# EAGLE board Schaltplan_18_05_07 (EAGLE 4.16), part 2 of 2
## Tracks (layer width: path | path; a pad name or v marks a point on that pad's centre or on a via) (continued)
N$105  (via drill 0.5) (continued)
  Top 0.305: R39.2 232.41,43.18 233.07,42.52 S3.P$1 233.04,35.56 235.59,33.02 235.59,9.53 233.68,7.62 224.79,7.62 222.57,5.4 186.06,5.4 182.88,8.57 182.88,35.56 177.8,40.64 177.8,53.98 184.78,60.96 184.78,67.94 189.87,73.03 193.68,73.03 194.31,72.39 v194.31,71.12 | IC15.3 v194.31,68.58
  Bottom 0.305: v194.31,68.58 v194.31,71.12
N$106  (via drill 0.5)
  Top 0.305: v229.87,31.11 S3.P$2 | v161.93,53.98 146.69,69.22 IC13.2
  Bottom 0.305: v229.87,31.11 223.52,24.77 191.13,24.77 v161.93,53.98
N$107
  Top 0.305: IC15.2 195.58,64.77 196.22,64.14 201.29,64.14 C26.2
N$108  (via drill 0.5)
  Top 0.305: 228.6,14.61 T3.1 | 228.6,43.81 R41.2 228.6,14.61 | C26.1 201.29,71.12 198.12,74.3 188.59,74.3 182.88,68.58 182.88,60.96 176.53,54.61 176.53,40.01 181.61,34.92 181.61,8.26 185.42,4.45 224.16,4.45 226.06,6.35 v228.6,6.35 | v228.6,11.43 228.6,14.61
  Bottom 0.305: v228.6,6.35 v228.6,11.43
N$109  (via drill 0.5)
  Top 0.305: 215.26,50.8 217.17,52.7 223.44,52.7 D13.A 225.43,50.8 v222.88,50.8 | D12.C 215.26,50.8 | 215.26,50.8 v212.09,50.8 | 248.92,53.34 R42.2 v246.38,53.34 | v149.86,71.75 IC13.4
  Bottom 0.305: v222.88,50.8 243.84,50.8 v246.38,53.34 | v212.09,50.8 170.81,50.8 v149.86,71.75
N$110  (via drill 0.5)
  Top 0.305: D15.C 240.66,50.8 238.76,52.7 228.6,52.7 227.97,52.07 227.97,48.26 | 220.34,48.26 227.97,48.26 | 220.34,50.8 D14.A 220.34,48.26 | R43.2 236.22,46.35 234.31,48.26 227.97,48.26 | v217.81,48.26 220.34,48.26 | v149.86,73.03 IC13.5
  Bottom 0.305: v217.81,48.26 217.81,50.8 214.63,53.98 200.03,53.98 198.12,55.88 167,55.88 v149.86,73.03
N$111  (via drill 0.5 pad 0.3)
  Top 0.305: 236.22,43.81 R43.1 v236.22,41.91
  Bottom 0.305: B_P7.7.1 252.73,30.48 246.38,30.48 236.22,40.64 v236.22,41.91
N$112
  Top 0.305: T3.3 233.68,13.34 229.24,8.89 224.79,8.89 223.52,10.16 223.52,34.29 224.79,35.56 S3.P$3 | S3.P$3 226.69,35.56 | R40.1 224.79,43.81 226.67,41.94 S3.P$3
N$113
  Top 0.305: R45.1 59.05,104.78 R44.E
N$114
  Top 0.305: SPEAKER.- 42.86,121.92 43.81,122.87 60.33,122.87 61.28,121.92 61.28,104.78 R45.2
N$115
  Top 0.305: 189.87,52.07 IC14.8 189.87,50.16 | 189.87,50.16 204.44,35.59 | 204.44,35.59 204.47,35.56 | 189.87,50.16 185.42,50.16 184.78,50.8 IC14.12 184.78,52.07 | S2.P$3 208.28,35.56 208.28,35.59 204.44,35.59
N$116
  Top 0.305: IC14.10 187.32,52.07 187.22,51.97 IC14.11
N$117
  Top 0.305: T2.3 213.68,14.61 212.72,15.56 212.72,29.84 | R47.1 209.55,43.81 214.66,38.71 S2.P$1 214.63,35.56 214.63,30.48 214,29.84 212.72,29.84 | IC14.13 183.51,50.16 184.15,49.53 189.23,49.53 208.91,29.84 212.72,29.84
N$118  (via drill 0.5)
  Top 0.305: S1.P$1 196.22,35.56 | S1.P$1 198.12,35.56 199.39,34.29 199.39,15.88 198.12,14.61 T1.3 196.85,9.53 198.12,8.26 216.85,8.26 218.44,9.84 218.44,38.52 R36.1 | S1.P$1 196.24,38.71 v193.68,41.27 | v189.23,41.27 188.59,41.27 187.32,42.55 IC14.5
  Bottom 0.305: v193.68,41.27 v189.23,41.27
N$119  (via drill 0.5, 0.5 pad 0.3)
  Top 0.305: R59.2 170.81,69.85 169.54,71.12 v168.28,71.12 | v163.19,71.12 JP7.2 155.57,68.58 v152.4,65.41 | IC13.19 120.65,69.22 121.28,68.58 v121.28,65.09 | IC13.1 129.54,67.94 v129.54,65.09
  Bottom 0.305: v163.19,71.12 v168.28,71.12 | v121.28,65.09 v129.54,65.09 152.08,65.09 v152.4,65.41
N$120  (via drill 0.5)
  Top 0.305: T2.1 203.2,14.61 201.93,15.88 v201.93,31.75 | v201.93,40.32 201.93,43.81 | IC14.9 188.59,53.34 189.23,53.98 195.58,53.98 196.85,52.7 196.85,45.09 198.12,43.81 201.93,43.81 | 201.93,43.81 R46.1
  Bottom 0.305: v201.93,31.75 v201.93,40.32
N$121
  Top 0.305: B_P7.6.1 252.73,53.34 R42.1 250.19,53.34
N$122
  Top 0.305: R48.1 254,5.71 B_P3.3.1
N$123  (via drill 0.5)
  Top 0.305: IC17.1 43.18,67.94 C34.+ C33.+ 43.19,74.29 42.55,74.93 38.73,74.93 38.1,75.56 38.1,76.83 37.47,77.47 v31.75,77.47 31.75,74.3 C32.1 | JP9.1 10.79,64.14 13.97,67.31 20.95,67.31 v24.13,70.48
  Bottom 0.305: v24.13,70.48 30.8,70.48 31.75,71.44 v31.75,77.47
N$125
  Top 0.305: 33.02,98.42 R49.2 OK1.3
N$126  (via drill 0.5)
  Top 0.305: OK1.6 24.13,98.42 25.4,97.16 31.11,97.16 v32.38,95.89 32.38,93.34 R50.2 | IC16.1 43.81,99.06 43.18,98.42 38.73,98.42 38.1,97.79 v38.1,95.89
  Bottom 0.305: v32.38,95.89 v38.1,95.89
N$127
  Top 0.305: OK2.3 17.78,81.92 16.51,83.19 16.51,98.42 17.78,99.69 22.23,99.69 26.67,104.14 R51.1
N$128
  Top 0.305: R51.2 39.37,104.14 40.01,103.5 IC16.4 40.01,100.97
N$129
  Top 0.305: L10.1 40.01,85.09 38.73,86.36 36.2,86.36 34.92,87.63 34.92,98.42 R49.1
N$130
  Top 0.305: L11.1 39.96,78.15 39.01,78.15 35.24,81.92 32.7,81.92 R52.1 32.7,82.23 32.38,81.92 OK2.6
N$131  (via drill 0.5)
  Top 0.305: v38.1,93.34 40.64,93.34 41.27,93.98 IC16.6 | CAN.2 15.04,87.2 v15.24,87
  Bottom 0.305: v38.1,93.34 38.1,90.81 36.83,89.53 17.78,89.53 v15.24,87
N$132
  Top 0.305: 6.99,71.75 6.99,95.89 8.08,96.98 11.25,96.98 11.43,97.16 CAN.G1 | 6.99,71.75 11.43,71.75 CAN.G2 | 6.99,71.75 6.99,69.22 2.54,64.77 2.54,60.96 3.81,59.69 12.06,59.69 13.34,60.96 13.34,64.14 15.24,66.04 20.32,66.04 22.23,64.14 22.23,62.23 23.81,60.64 30.16,60.64 31.75,62.23 31.75,62.87 C37.1
N$133  (via drill 0.5)
  Top 0.305: CAN.7 13.87,85.83 v13.97,85.72 | 42.55,95.89 IC16.7 v42.55,93.34
  Bottom 0.305: v13.97,85.72 34.92,85.72 v42.55,93.34
N$134
  Top 0.305: S4.16 140.34,26.04 141.29,26.99 | R53.1 144.15,31.11 144.15,29.84 141.29,26.99 | 141.29,26.99 140.97,27.3 IC18.2
N$135
  Top 0.305: R54.1 144.78,34.92 145.41,34.29 145.41,29.21 142.88,26.67 S4.15 142.88,22.23 142.24,21.59 139.06,21.59 137.79,22.86 137.79,47.62 138.43,48.26 141.6,48.26 142.24,47.62 IC18.3
N$136
  Top 0.305: R55.1 144.78,38.73 146.69,36.83 146.69,28.57 145.41,27.3 S4.14 145.41,21.59 144.15,20.32 138.43,20.32 137.16,21.59 137.16,48.26 137.79,48.9 142.88,48.9 143.51,48.26 IC18.4
N$137
  Top 0.305: S4.13 147.96,38.1 144.78,41.27 144.78,41.91 | R56.1 144.78,42.55 144.78,41.91 | 144.78,41.91 IC18.5
N$138
  Top 0.305: S4.12 150.5,42.55 | 154.94,42.55 R57.1 150.5,42.55 | IC18.6 146.05,43.18 146.69,42.55 150.5,42.55
N$139
  Top 0.305: 154.94,38.73 R58.1 153.67,38.73 151.76,36.83 151.76,28.57 153.03,27.3 S4.11 153.03,20.95 151.13,19.05 137.79,19.05 136.53,20.32 136.53,48.9 137.16,49.53 146.69,49.53 147.32,48.9 IC18.7
N$140  (via drill 0.5)
  Top 0.305: S4.10 155.57,26.67 153.03,29.21 153.03,34.29 153.67,34.92 R60.1 154.94,34.92 | IC18.8 148.59,49.53 147.96,50.16 136.53,50.16 135.89,49.53 v135.89,18.41
  Bottom 0.305: v135.89,18.41 135.89,20.95 136.84,21.91 154.62,21.91 155.57,22.86 S4.10
N$141
  Top 0.305: R61.1 154.94,31.11 154.94,29.21 158.12,26.04 S4.9 158.12,43.18 157.48,43.81 150.5,43.81 149.86,44.45 IC18.9
N$144  (via drill 0.5)
  Top 0.305: v139.7,43.18 IC18.1 | IC18.19 140.97,55.24 | IC18.19 140.97,55.88 | IC18.19 v140.97,51.44 JP10.1 v161.93,51.44 | R62.1 161.93,31.11 v161.93,46.99
  Bottom 0.305: v139.7,43.18 140.97,44.45 v140.97,51.44 | v161.93,51.44 v161.93,46.99
N$145
  Top 0.305: I2C.5 7.62,46.99 8.26,46.35 JP11.1
N$146
  Top 0.305: JP13.1 16.51,46.35 15.24,47.62 10.79,47.62 8.89,49.53 I2C.7
N$147
  Top 0.305: JP12.2 22.86,49.53 21.59,50.8 5.71,50.8 I2C.10
N$148  (via drill 0.5, 0.5 pad 0.3)
  Top 0.305: v149.54,74.61 149.22,74.61 147,76.83 IC13.8 | v211.46,39.37 S2.P$2 | v205.42,55.24 v205.42,48.9
  Bottom 0.305: v149.54,74.61 149.86,74.61 150.18,74.3 166.69,57.47 203.2,57.47 v205.42,55.24 | v211.46,39.37 205.42,45.4 v205.42,48.9
N$151
  Top 0.813: D9.A 234.95,102.23 236.18,103.47 C9.- 238.12,107.95 240.03,109.86 240.03,129.54 237.49,132.08 235.16,132.08 C13.2 234.91,132.68 234.95,132.72 234.95,135.25 234.31,135.89 232.41,135.89 230.5,133.99 227.88,133.99 L2.1
N$153  (via drill 0.5)
  Top 0.305: v36.2,64.77 37.47,66.04 IC17.3 38.73,63.5 40.01,62.23 40.64,62.23 46.35,67.94 46.35,88.27 45.09,89.53 C35.+ | 27.94,62.87 27.94,63.5 29.21,64.77 v31.75,64.77 | CAN.9 10.16,76.83 11.43,75.56 14.61,75.56 15.24,74.93 v15.24,71.75 | v24.13,65.41 24.13,62.23 24.77,61.59 27.3,61.59 27.94,62.23 27.94,62.87 | 27.94,62.87 C31.1
  Bottom 0.305: v31.75,64.77 v36.2,64.77 | v15.24,71.75 17.78,71.75 v24.13,65.41
NETZ  (via drill 0.9)
  Top 0.813: IC1.IN 245.07,158.71 C3.+ 247.65,149.86 248.28,149.22 248.28,146.69 | 248.28,146.69 243.21,146.69 242.57,146.05 242.57,141.6 241.3,140.34 233.17,140.34 | 233.17,140.34 233.04,140.34 | 253.37,134.62 253.37,145.41 252.09,146.69 248.28,146.69 | D9.C 232.41,102.23 231.14,103.5 231.14,107.95 C9.+ 228.35,107.95 v226.57,109.73 | v226.57,116.33 226.57,120.78 223.01,124.97 223.01,125.98 222.84,126.16 L1.1 222.84,127.34 225.17,129.67 228.35,129.67 230.89,132.33 C13.1 233.21,134.07 v233.17,134.11 | C6.1 258.53,125.94 258.57,125.98 260.1,125.98 261.11,127 261.11,130.56 260.22,131.44 IC2.IN 258.44,132.72 256.54,134.62 253.37,134.62 | C1.+ 244.47,134.49 244.35,134.62 253.37,134.62 | v233.17,140.21 233.17,140.34 | C4.1 233.26,140.55 233.04,140.34 | 233.04,140.34 227.33,140.34 225.43,142.24 F2.2A
  Bottom 0.813: v226.57,109.73 v226.57,116.33 | v233.17,134.11 v233.17,140.21
P2.0  (via drill 0.5 pad 0.3)
  Top 0.305: IC10.2 96.52,90.81 97.79,92.08 v176.85,92.08 | JP4.P$19 206.38,173.99 207.01,173.35 207.01,140.34 205.74,139.06 v190.5,139.06 | v189.23,103.19 v189.23,109.86
  Bottom 0.305: v190.5,139.06 190.5,111.12 v189.23,109.86 168.91,109.86 168.28,109.22 MM_C1.120 | v189.23,103.19 189.23,93.03 188.28,92.08 v176.85,92.08
P2.1  (via drill 0.5, 0.5 pad 0.3)
  Top 0.305: v95.25,91.12 IC10.3 | JP4.P$21 203.84,173.99 204.47,173.35 204.47,141.6 203.2,140.34 v191.77,140.34 | v168.28,91.12 v98.42,91.12
  Bottom 0.305: v98.42,91.12 v95.25,91.12 | v191.77,140.34 191.77,109.86 190.5,108.58 170.18,108.58 169.54,107.95 169.54,103.5 168.28,102.23 MM_C1.119 v168.28,91.12
P2.2  (via drill 0.5, 0.5 pad 0.3)
  Top 0.305: v93.98,90.17 IC10.4 | v169.54,90.17 v97.47,90.17 | JP4.P$23 201.29,173.99 201.93,173.35 201.93,142.88 200.66,141.6 v193.04,141.6
  Bottom 0.305: v97.47,90.17 v93.98,90.17 | v193.04,141.6 193.04,108.9 192.09,107.95 171.45,107.95 170.81,107.31 MM_C1.122 | MM_C1.122 170.81,103.82 | v169.54,90.17 169.54,102.23 170.81,103.5 MM_C1.122
P2.3  (via drill 0.5, 0.5 pad 0.3)
  Top 0.305: v92.71,89.22 IC10.5 | v170.81,89.22 v98.42,89.22 | JP4.P$25 198.75,173.99 199.39,173.35 199.39,144.15 198.12,142.88 v194.31,142.88
  Bottom 0.305: v98.42,89.22 v92.71,89.22 | v194.31,142.88 194.31,108.58 193.04,107.31 172.72,107.31 172.09,106.68 172.09,103.5 170.81,102.23 MM_C1.121 v170.81,89.22
P2.4  (via drill 0.5, 0.5 pad 0.3)
  Top 0.305: v91.44,88.27 IC10.6 | v172.09,88.27 v97.47,88.27 | JP4.P$27 196.22,173.99 196.85,173.35 196.85,145.41 v195.58,144.15
  Bottom 0.305: v97.47,88.27 v91.44,88.27 | v195.58,144.15 195.58,107.95 194.31,106.68 173.99,106.68 173.35,106.05 MM_C1.124 173.35,103.5 172.09,102.23 v172.09,88.27
P2.5  (via drill 0.5, 0.5 pad 0.3)
  Top 0.305: v173.35,87.31 v98.42,87.31 | v90.17,87.31 IC10.7 | JP4.P$29 193.68,173.99 194.31,173.35 194.31,146.69 v194.31,146.05
  Bottom 0.305: v98.42,87.31 v90.17,87.31 | v173.35,87.31 MM_C1.123 173.35,102.23 174.62,103.5 174.62,105.41 175.26,106.05 195.58,106.05 196.85,107.31 196.85,145.41 196.22,146.05 v194.31,146.05
P2.6  (via drill 0.5, 0.5 pad 0.3)
  Top 0.305: v88.9,86.36 IC10.8 | v174.62,86.36 v97.47,86.36 | JP4.P$31 191.13,173.99 191.77,173.35 191.77,149.22 v191.77,147.96
  Bottom 0.305: v97.47,86.36 v88.9,86.36 | v174.62,86.36 174.62,102.23 175.9,103.5 MM_C1.126 175.9,104.78 176.53,105.41 196.85,105.41 198.12,106.68 198.12,147.32 197.49,147.96 v191.77,147.96
P2.7  (via drill 0.5, 0.5 pad 0.3)
  Top 0.305: v87.63,85.72 IC10.9 | v175.9,85.41 v98.42,85.41 | JP4.P$33 188.59,173.99 189.23,173.35 v189.23,149.86
  Bottom 0.305: v98.42,85.41 87.95,85.41 v87.63,85.72 | v175.9,85.41 MM_C1.125 175.9,102.23 176.53,102.87 180.34,102.87 182.25,104.78 198.12,104.78 199.39,106.05 199.39,149.22 198.75,149.86 v189.23,149.86
P2.8  (via drill 0.5 pad 0.3, 0.5 pad 0.41)
  Top 0.305: IC13.12 117.47,78.11 116.84,78.74 116.84,80.01 117.47,80.64 147.32,80.64 151.13,76.83 v176.85,76.83 | 186.69,76.83 186.85,76.99 | 186.85,76.99 193.99,84.45 v193.99,90.17 | JP4.P$35 186.06,173.99 186.69,173.35 v186.69,152.4 176.85,152.4 175.9,151.45 MM_C1.3 | 186.69,76.83 186.85,76.99 | 186.85,76.99 | v181.29,76.83 186.69,76.83
  Bottom 0.305: v193.99,90.17 193.99,101.6 195.26,102.87 201.93,102.87 203.2,104.14 203.2,151.76 202.56,152.4 v186.69,152.4 | v181.29,76.83 v176.85,76.83
P2.9
  Top 0.305: JP4.P$37 182.25,173.99 181.61,173.35 181.61,170.18 174.62,163.19 174.62,147.96 175.26,147.32 MM_C1.4
P2.10
  Top 0.305: JP4.P$39 179.71,173.99 179.07,173.35 179.07,170.18 173.35,164.47 MM_C1.5
P2.11
  Top 0.305: JP4.P$41 177.8,173.35 176.53,172.09 176.53,170.18 172.09,165.74 172.09,147.96 172.72,147.32 MM_C1.6
P2.12
  Top 0.305: JP4.P$43 174.62,173.99 173.99,173.35 173.99,170.18 170.81,167 MM_C1.7
P2.13
  Top 0.305: JP4.P$45 172.09,173.99 171.45,173.35 171.45,170.18 169.54,168.28 169.54,147.96 170.18,147.32 MM_C1.8
P2.14
  Top 0.305: JP4.P$47 169.54,173.99 168.91,173.35 168.91,170.18 168.28,169.54 MM_C1.9
P2.15
  Top 0.305: MM_C1.10 167.64,147.32 167,147.96 167,170.18 166.37,170.81 166.37,173.35 167,173.99 JP4.P$49
P3.0
  Bottom 0.305: JP4.P$20 205.74,161.29 204.47,160.02 168.28,160.02 167,158.75 167,147.96 166.37,147.32 MM_C1.12
P3.1
  Bottom 0.305: JP4.P$22 203.2,161.93 201.93,160.66 167,160.66 165.74,159.38 MM_C1.11
P3.2
  Bottom 0.305: JP4.P$24 200.66,162.56 199.39,161.29 165.74,161.29 164.47,160.02 164.47,149.22 163.19,147.96 MM_C1.14
P3.3  (via drill 0.5 pad 0.3)
  Top 0.305: 119.38,79.38 IC13.11 | 119.38,79.38 118.75,79.38 | 119.38,79.38 123.19,79.38 124.46,78.11 v124.46,64.14 | v137.79,67.63 139.7,65.72 v139.7,64.14 | v154.31,121.6 v154.31,139.7
  Bottom 0.305: JP4.P$26 198.12,163.19 196.85,161.93 164.47,161.93 163.19,160.66 MM_C1.13 163.19,149.22 161.93,147.96 161.93,140.65 160.97,139.7 v154.31,139.7 | 133.35,64.14 v124.46,64.14 135.25,64.14 v139.7,64.14 | v137.79,67.63 137.79,83.82 154.31,100.33 v154.31,121.6
P3.4  (via drill 0.5, 0.5 pad 0.3)
  Top 0.305: v139.7,67.63 142.24,65.09 IC18.18 | v164.15,125.41 164.15,143.83 165.1,144.78 194.63,144.78 195.58,145.73 v195.58,163.83
  Bottom 0.305: MM_C1.16 160.66,147.96 161.93,149.22 161.93,161.29 163.19,162.56 194.31,162.56 v195.58,163.83 JP4.P$28 | v139.7,67.63 139.7,83.19 156.84,100.33 156.84,124.46 157.8,125.41 v164.15,125.41
P3.5  (via drill 0.5, 0.5 pad 0.3)
  Top 0.305: v141.6,67.63 143.51,65.72 IC18.17 | v161.93,124.46 161.93,149.22 161.29,149.86 MM_C1.15
  Bottom 0.305: JP4.P$30 193.04,164.47 191.77,163.19 161.93,163.19 160.66,161.93 MM_C1.15 | v141.6,67.63 141.6,82.55 159.38,100.33 159.38,123.51 160.34,124.46 v161.93,124.46
P3.6  (via drill 0.5, 0.5 pad 0.3)
  Top 0.305: v143.51,67.63 144.78,66.36 IC18.16 | v161.93,122.87 160.34,122.87 159.38,123.83 159.38,146.69 158.75,147.32 MM_C1.18
  Bottom 0.305: JP4.P$32 190.5,165.1 189.23,163.83 160.66,163.83 159.38,162.56 159.38,147.96 158.75,147.32 MM_C1.18 | v143.51,67.63 143.51,81.92 161.93,100.33 v161.93,122.87
P3.7  (via drill 0.5, 0.5 pad 0.3)
  Top 0.305: v145.41,67.63 146.05,66.99 IC18.15 | v164.47,121.92 157.8,121.92 156.84,122.87 156.84,149.22 157.48,149.86 MM_C1.17
  Bottom 0.305: JP4.P$34 187.96,165.74 186.69,164.47 159.38,164.47 158.12,163.19 MM_C1.17 | v145.41,67.63 145.41,81.6 164.47,100.65 v164.47,121.92
P3.8  (via drill 0.5 pad 0.3)
  Top 0.305: v147.32,66.99 IC18.14 | v167,121.92 167,142.88 167.96,143.83 v185.42,143.83 | v185.42,153.35 v185.42,166.37
  Bottom 0.305: JP4.P$36 185.42,167 v185.42,166.37 184.15,165.1 158.12,165.1 156.84,163.83 156.84,147.96 156.21,147.32 MM_C1.20 | v147.32,66.99 147.32,81.28 167,100.97 v167,121.92 | v185.42,143.83 v185.42,153.35
P3.9  (via drill 0.5 pad 0.3)
  Top 0.305: v148.59,66.04 IC18.13 | v190.5,103.19 190.5,111.76 189.55,112.71 v182.88,112.71 | v182.88,155.26 v182.88,167
  Bottom 0.305: JP4.P$38 182.88,167.64 v182.88,167 181.61,165.74 156.84,165.74 155.57,164.47 MM_C1.19 | v148.59,66.04 148.59,80.33 150.81,82.55 188.59,82.55 190.18,84.14 190.18,102.87 v190.5,103.19 | v182.88,112.71 v182.88,155.26
P3.10  (via drill 0.5 pad 0.3)
  Top 0.305: v149.86,60.96 IC18.12 | v138.43,60.96 138.43,65.09 v135.89,67.63 | v151.76,121.6 151.76,146.69 152.4,147.32 MM_C1.22
  Bottom 0.305: JP4.P$40 180.34,167.64 179.07,166.37 155.57,166.37 154.31,165.1 154.31,149.22 153.03,147.96 MM_C1.22 | v138.43,60.96 v149.86,60.96 | v135.89,67.63 135.89,84.45 151.76,100.33 v151.76,121.6
P3.11  (via drill 0.5 pad 0.3)
  Top 0.305: v151.13,59.37 IC18.11 | v137.16,59.37 137.16,64.45 v133.99,67.63 | v150.5,121.6 v150.5,141.92 | v154.31,141.92 154.31,149.22 153.67,149.86 MM_C1.21
  Bottom 0.305: JP4.P$42 177.8,168.28 176.53,167 154.31,167 153.03,165.74 MM_C1.21 | v137.16,59.37 v151.13,59.37 | v133.99,67.63 133.99,84.14 149.22,99.38 149.22,106.36 150.5,107.63 v150.5,121.6 | v150.5,141.92 v154.31,141.92
P3.12  (via drill 0.5 pad 0.3)
  Top 0.305: v80.01,175.26 v73.34,175.26 | v142.56,175.26 145.41,175.26 175.9,175.26 176.53,174.62 176.53,173.35 175.26,172.09 JP4.P$44
  Bottom 0.305: JP4.P$44 175.26,168.91 173.99,167.64 153.03,167.64 151.76,166.37 151.76,147.96 151.13,147.32 MM_C1.24 | JP3.P$44 23.81,171.45 22.86,172.4 22.86,174.62 23.5,175.26 v73.34,175.26 | v80.01,175.26 v142.56,175.26
P3.13
  Bottom 0.305: JP4.P$46 172.72,169.54 171.45,168.28 151.76,168.28 150.5,167 MM_C1.23
P3.15
  Bottom 0.305: JP4.P$50 167.64,170.18 166.37,168.91 149.22,168.91 147.96,167.64 MM_C1.25
P5.0  (via drill 0.5 pad 0.3)
  Top 0.305: 81.92,83.5 IC9.11 81.92,85.72 89.22,93.03 v126.36,93.03 v177.8,93.03 | MM_C1.132 174.62,114.3 173.99,113.67 173.99,110.49 175.26,109.22 184.78,109.22 185.42,108.58 v185.42,93.03 196.53,93.03 200.03,96.52 200.03,109.22 214,123.19 214,162.56 215.26,163.83 220.98,163.83 222.25,165.1 222.25,173.35 222.88,173.99 JP4.P$5 | JP5.P$19 124.46,173.99 125.09,173.35 125.09,152.72 126.36,151.45 v126.36,121.6
  Bottom 0.305: v177.8,93.03 v185.42,93.03 | v126.36,93.03 v126.36,121.6
P5.1  (via drill 0.5 pad 0.3)
  Top 0.305: IC9.12 80.64,85.72 88.9,93.98 v116.2,93.98 v176.85,93.98 | MM_C1.134 173.99,116.84 173.35,116.2 173.35,109.86 174.62,108.58 183.83,108.58 184.47,107.95 v184.47,93.98 184.47,92.08 185.1,91.44 196.53,91.44 208.28,103.19 208.28,116.2 214.63,122.56 214.63,161.93 215.9,163.19 222.25,163.19 223.52,164.47 JP4.P$6 | JP5.P$21 121.92,173.99 122.56,173.35 122.56,153.67 120.97,152.08 117.16,152.08 116.2,151.13 v116.2,121.6
  Bottom 0.305: v116.2,121.6 v116.2,93.98 | v176.85,93.98 v184.47,93.98
P5.2  (via drill 0.5 pad 0.3)
  Top 0.305: IC9.13 79.38,85.72 88.58,94.93 110.81,94.93 | v183.51,94.93 183.51,107.31 182.88,107.95 173.99,107.95 172.72,109.22 172.72,118.75 173.35,119.38 MM_C1.136 | JP4.P$7 220.34,173.99 219.71,173.35 219.71,166.37 218.44,165.1 214,165.1 212.72,163.83 212.72,124.46 197.49,109.22 197.49,100.33 196.22,99.06 187.96,99.06 187.32,98.42 v187.32,94.93 | JP5.P$23 119.38,173.99 120.02,173.35 120.02,154.94 118.43,153.35 112.08,153.35 111.12,152.4 v111.12,121.6 | v111.12,94.93 110.81,94.93 | 110.81,94.93 v177.8,94.93
  Bottom 0.305: v187.32,94.93 v183.51,94.93 v177.8,94.93 | v111.12,121.6 v111.12,94.93
P5.3  (via drill 0.5 pad 0.3)
  Top 0.305: IC9.14 78.11,85.72 88.27,95.89 v106.05,95.89 v176.85,95.89 | v182.56,95.89 182.56,106.68 181.93,107.31 173.35,107.31 172.09,108.58 172.09,121.28 172.72,121.92 MM_C1.138 | JP4.P$8 220.98,165.74 219.71,164.47 214.63,164.47 213.36,163.19 213.36,123.83 198.75,109.22 198.75,97.47 197.17,95.89 v188.28,95.89 | JP5.P$25 116.84,173.99 117.47,173.35 117.47,156.53 115.57,154.62 107,154.62 106.05,153.67 v106.05,121.6
  Bottom 0.305: v188.28,95.89 v182.56,95.89 v176.85,95.89 | v106.05,121.6 v106.05,95.89
P5.4  (via drill 0.5 pad 0.3)
  Top 0.305: IC9.15 76.83,85.72 87.95,96.84 v97.16,96.84 v177.8,96.84 | v181.61,96.84 181.61,106.05 180.97,106.68 172.72,106.68 171.45,107.95 171.45,123.83 172.09,124.46 MM_C1.140 | JP4.P$9 217.81,173.99 217.17,173.35 217.17,167.64 215.9,166.37 212.72,166.37 211.46,165.1 211.46,125.73 194.94,109.22 194.94,102.87 193.68,101.6 187.01,101.6 186.37,100.97 v186.37,96.84 | JP5.P$27 114.3,173.99 114.94,173.35 114.94,157.48 113.35,155.89 101.92,155.89 100.97,154.94 100.97,125.09 97.47,121.6 v97.16,121.6
  Bottom 0.305: v186.37,96.84 v181.61,96.84 v177.8,96.84 | v97.16,121.6 v97.16,96.84
P5.5  (via drill 0.5 pad 0.3)
  Top 0.305: 75.56,85.41 IC9.16 | 75.56,85.41 87.95,97.79 v176.85,97.79 | v180.66,97.79 180.66,105.41 180.02,106.05 172.4,106.05 170.81,107.63 170.81,126.36 171.45,127 MM_C1.142 | JP4.P$10 218.44,167 217.17,165.74 213.36,165.74 212.09,164.47 212.09,125.09 196.22,109.22 196.22,101.6 194.94,100.33 v187.96,100.33 | JP5.P$29 111.76,173.99 112.39,173.35 112.39,158.75 110.81,157.16 98.11,157.16 96.84,155.89 v96.84,128.91 | v75.88,128.91 75.56,128.59 v75.56,92.39 | v75.56,87 75.56,85.41
  Bottom 0.305: v187.96,100.33 181.29,100.33 180.66,99.69 v180.66,97.79 v176.85,97.79 | v96.84,128.91 v75.88,128.91 | v75.56,92.39 v75.56,87
P5.6  (via drill 0.5 pad 0.3)
  Top 0.305: JP4.P$11 215.26,173.99 214.63,173.35 214.63,168.91 213.36,167.64 211.46,167.64 210.19,166.37 210.19,132.08 208.91,130.81 v181.61,130.81 176.53,130.81 175.9,130.18 MM_C1.144 | JP5.P$31 109.22,173.99 109.86,173.35 109.86,159.7 108.58,158.43 96.2,158.43 94.93,157.16 v94.93,129.86 | v74.93,129.86 74.3,129.22 v74.3,92.39 | v74.3,87 IC9.17
  Bottom 0.305: v74.93,129.86 v94.93,129.86 95.89,130.81 147.64,130.81 149.86,133.03 165.42,133.03 170.81,127.64 170.81,113.98 171.77,113.03 180.66,113.03 181.61,113.98 v181.61,130.81 | v74.3,92.39 v74.3,87
P5.7  (via drill 0.5 pad 0.3)
  Top 0.305: JP4.P$12 215.9,168.28 214.63,167 212.09,167 210.82,165.74 210.82,129.54 209.55,128.27 174.62,128.27 173.99,128.91 173.99,129.86 | MM_C1.146 174.62,132.08 173.99,131.44 173.99,129.86 | JP5.P$33 106.68,173.99 107.31,173.35 107.31,160.97 106.05,159.7 94.3,159.7 93.03,158.43 v93.03,130.81 | v73.98,130.81 73.03,129.86 v73.03,92.39 | v73.03,87 IC9.18 | v170.5,129.86 173.99,129.86
  Bottom 0.305: v73.98,130.81 v93.03,130.81 93.66,131.44 147.32,131.44 149.54,133.67 167.32,133.67 170.5,130.49 v170.5,129.86 | v73.03,92.39 v73.03,87
P5.8  (via drill 0.5 pad 0.3)
  Top 0.305: JP4.P$13 212.72,173.99 212.09,173.35 212.09,170.81 208.91,167.64 208.91,137.16 207.65,135.89 v201.93,135.89 176.53,135.89 175.9,135.25 MM_C1.148 | v114.94,70.48 IC13.18 | v114.94,80.33 116.2,81.6 148.27,81.6 151.76,78.11 v176.85,78.11 | v192.72,88.27 192.72,84.77 186.06,78.11 v181.29,78.11 | JP5.P$35 104.14,173.99 104.78,173.35 104.78,162.24 103.5,160.97 92.39,160.97 91.12,159.7 91.12,107 90.49,106.36 v86.36,106.36
  Bottom 0.305: v114.94,70.48 v114.94,80.33 105.09,80.33 104.14,81.28 104.14,91.76 103.19,92.71 87.63,92.71 86.68,93.66 v86.36,106.36 | v192.72,88.27 192.72,102.23 193.99,103.5 200.66,103.5 201.93,104.78 v201.93,135.89 | v181.29,78.11 v176.85,78.11
P5.9  (via drill 0.5, 0.5 pad 0.3)
  Top 0.305: v170.81,41.91 B_P5.9.1 | JP4.P$14 213.36,170.81 209.55,167 209.55,134.62 208.28,133.35 v200.66,133.35 174.62,133.35 173.99,133.99 173.99,136.53 174.62,137.16 MM_C1.150 | v113.67,79.38 113.67,81.28 114.94,82.55 149.22,82.55 152.4,79.38 v176.85,79.38 | v191.45,90.17 191.45,85.41 185.42,79.38 v181.29,79.38 | JP5.P$37 101.6,173.99 102.23,173.35 102.23,163.51 100.97,162.24 90.49,162.24 89.22,160.97 89.22,108.27 88.27,107.31 85.09,107.31 84.45,106.68 v84.45,106.36 | v113.67,71.75 IC13.17 v113.67,71.75
  Bottom 0.305: v170.81,41.91 133.99,41.91 113.67,62.87 v113.67,71.75 v113.67,79.38 103.82,79.38 102.87,80.33 102.55,91.12 101.6,92.08 85.41,92.08 84.45,93.03 v84.45,106.36 | v191.45,90.17 191.45,102.87 192.72,104.14 199.39,104.14 200.66,105.41 v200.66,133.35 | v176.85,79.38 v181.29,79.38
P5.10  (via drill 0.5 pad 0.3, 0.6 pad 0.3)  (1 unrouted)
  Top 0.305: JP5.P$39 99.06,173.99 99.69,173.35 99.69,164.78 98.42,163.51 88.58,163.51 87.31,162.24 v87.31,131.76 | MM_C1.131 198.75,114.3 207.33,122.87 v207.33,123.51 | D1.A 210.19,79.38 v207.33,79.38
  Top 0.406: R2.2 215.26,80.64 213.91,79.29 D1.A
  Top 0.61: D1.A 210.19,75.56
  Bottom 0.305: v87.31,131.76 89.22,132.08 147,132.08 149.22,134.3 167.96,134.3 171.45,130.81 171.45,116.52 172.4,115.57 177.8,115.57 178.44,114.94 MM_C1.131 | v207.33,123.51 v207.33,79.38
P5.11  (via drill 0.5 pad 0.3)
  Top 0.305: JP5.P$41 96.52,173.99 97.16,173.35 97.16,166.05 95.89,164.78 86.68,164.78 85.41,163.51 v85.41,132.4
  Bottom 0.305: v85.41,132.4 87,132.72 146.69,132.72 148.91,134.94 168.59,134.94 172.09,131.44 172.09,121.28 172.72,120.65 177.8,120.65 178.44,120.02 MM_C1.135
P5.12  (via drill 0.5 pad 0.3, 0.6 pad 0.3)  (1 unrouted)
  Top 0.305: JP5.P$43 93.98,173.99 94.61,173.35 94.61,167.32 93.34,166.05 84.77,166.05 83.5,164.78 v83.5,133.03 | MM_C1.139 v205.74,124.46
  Top 0.406: R4.2 212.94,60.33 210.82,60.33 | D4.C 207.09,60.24 205.74,61.59 v205.74,88.9 210.19,88.9
  Top 0.61: 210.19,88.9 D2.A
  Bottom 0.305: v83.5,133.03 84.77,133.35 146.37,133.35 148.59,135.57 169.23,135.57 172.72,132.08 172.72,126.68 173.67,125.73 177.8,125.73 178.44,125.09 MM_C1.139 | v205.74,124.46 v205.74,88.9
P5.13  (via drill 0.5 pad 0.3)
  Top 0.305: JP5.P$45 91.44,173.99 92.08,173.35 92.08,168.59 90.81,167.32 82.87,167.32 81.6,166.05 v81.6,133.67
  Bottom 0.305: v81.6,133.67 82.55,133.99 146.05,133.99 148.27,136.21 169.86,136.21 175.26,130.81 177.8,130.81 178.44,130.18 MM_C1.143
P5.14  (via drill 0.5 pad 0.3)
  Top 0.305: JP5.P$47 88.9,173.99 89.53,173.35 89.53,169.86 88.27,168.59 80.96,168.59 79.69,167.32 v79.69,134.3
  Bottom 0.305: v79.69,134.3 80.01,134.62 145.73,134.62 147.96,136.84 173.04,136.84 173.99,135.89 177.8,135.89 178.44,135.25 MM_C1.147
P5.15  (via drill 0.5 pad 0.3)
  Top 0.305: JP5.P$49 86.36,173.99 87,173.35 87,171.13 85.72,169.86 79.69,169.86 78.42,168.59 78.42,148.27 77.79,147.64 v77.79,134.94
  Bottom 0.305: v77.79,134.94 78.11,135.25 145.1,135.25 147.64,137.79 172.72,137.79 173.35,138.43 173.35,141.29 174.31,142.24 177.8,142.24 178.44,141.6 MM_C1.151
P6.0  (via drill 0.5 pad 0.3)
  Top 0.305: JP5.P$5 142.24,173.99 142.88,173.35 142.88,159.07 144.15,157.8 149.22,157.8 150.5,156.53 150.5,152.72 149.22,151.45 v149.22,121.6
  Bottom 0.305: v149.22,121.6 146.69,119.06 146.69,100.33 143.19,96.84 131.13,96.84 130.18,97.79 MM_C1.89
P6.1  (via drill 0.5 pad 0.3)
  Top 0.305: JP5.P$6 141.6,156.21 146.69,151.13 v146.69,121.6
  Bottom 0.305: v146.69,121.6 144.15,119.06 144.15,100.01 141.92,97.79 132.08,97.79 131.44,98.42 131.44,103.5 130.81,104.14 MM_C1.90
P6.2  (via drill 0.5 pad 0.3)
  Top 0.305: JP5.P$7 139.7,173.99 140.34,173.35 140.34,155.26 144.15,151.45 v144.15,121.6
  Bottom 0.305: v144.15,121.6 142.56,121.6 141.6,120.65 141.6,99.38 140.97,98.74 133.35,98.74 132.72,99.38 MM_C1.91
P6.3  (via drill 0.5 pad 0.3)
  Top 0.305: JP5.P$8 139.06,153.99 141.6,151.45 141.6,146.05 139.06,143.51 v139.06,121.6
  Bottom 0.305: v139.06,121.6 139.06,100.33 138.43,99.69 134.62,99.69 133.99,100.33 133.99,102.23 132.72,103.5 MM_C1.92
P6.4  (via drill 0.5 pad 0.3)
  Top 0.305: JP5.P$9 137.48,173.99 138.11,173.35 138.11,153.35 139.06,152.4 139.06,146.05 137.79,144.78 v137.79,121.6
  Bottom 0.305: v137.79,121.6 137.79,106.05 136.53,104.78 136.53,102.23 135.89,101.6 MM_C1.93
P6.5  (via drill 0.5 pad 0.3)
  Top 0.305: v136.53,121.6 JP5.P$10
  Bottom 0.305: v136.53,121.6 136.53,106.36 135.25,105.09 MM_C1.94
P6.6  (via drill 0.5 pad 0.3)
  Top 0.305: JP5.P$11 133.35,173.99 132.72,173.35 132.72,152.72 131.44,151.45 v131.44,121.6 | v131.44,105.09 131.44,100.97 132.4,100.01 136.84,100.01 137.79,100.97 MM_C1.95
  Bottom 0.305: v131.44,121.6 v131.44,105.09
P6.7  (via drill 0.5 pad 0.3)
  Top 0.305: JP5.P$12 v133.99,121.6 | v133.99,105.09 133.99,103.5 134.62,102.87 137.16,102.87 137.79,103.5 MM_C1.96
  Bottom 0.305: v133.99,121.6 v133.99,105.09
P7.0  (via drill 0.5 pad 0.3)
  Top 0.305: MM_C1.104 147.96,105.73 147.32,106.36 v123.83,106.36 | JP5.P$20 v123.83,121.6
  Bottom 0.305: v123.83,121.6 v123.83,106.36
P7.1  (via drill 0.5 pad 0.3)
  Top 0.305: v127.64,108.27 149.86,108.27 150.5,107.63 MM_C1.106 | JP5.P$22 121.28,153.99 120.02,152.72 114.62,152.72 113.67,151.76 v113.67,129.22 | v127.64,121.6 v127.64,129.22
  Bottom 0.305: v127.64,108.27 v127.64,121.6 | v127.64,129.22 127.32,129.54 113.98,129.54 v113.67,129.22
P7.2  (via drill 0.5 pad 0.3)
  Top 0.305: v130.18,110.17 152.4,110.17 153.03,109.54 MM_C1.108 | JP5.P$24 118.75,155.89 116.84,153.99 109.54,153.99 108.58,153.03 v108.58,129.86 | v130.18,121.6 v130.18,129.86
  Bottom 0.305: v130.18,110.17 v130.18,121.6 | v130.18,129.86 129.86,130.18 108.9,130.18 v108.58,129.86
P7.3  (via drill 0.5 pad 0.3)
  Top 0.305: v125.09,112.08 154.94,112.08 155.57,111.44 MM_C1.110 | JP5.P$26 116.2,157.16 114.3,155.26 104.46,155.26 103.5,154.31 v103.5,126.05 | v125.09,126.36 v125.09,121.6
  Bottom 0.305: v125.09,121.6 v125.09,112.08 | v103.5,126.05 103.82,125.73 124.46,125.73 v125.09,126.36
P7.4  (via drill 0.5, 0.5 pad 0.3)
  Top 0.305: B_P7.4.1 170.81,6.67 168.59,4.45 133.35,4.45 132.08,5.71 v132.08,45.72 | 127.64,75.56 v127.64,62.87 | 129.54,75.56 IC13.7 127.64,75.56 | MM_C1.112 158.12,113.35 157.48,113.98 v128.91,113.98 v122.56,113.98 | JP5.P$28 113.67,158.12 112.08,156.53 99.06,156.53 97.79,155.26 97.79,128.59 v98.11,128.27 | v122.56,128.27 v122.56,121.6 | v127,75.56 127.64,75.56
  Bottom 0.305: v132.08,45.72 132.08,61.59 130.81,62.87 v127.64,62.87 | v122.56,121.6 v122.56,113.98 | v98.11,128.27 v122.56,128.27 | v127,75.56 127,82.55 128.91,84.45 v128.91,113.98
P7.5  (via drill 0.5 pad 0.3)
  Top 0.305: v95.89,115.89 160.02,115.89 160.66,115.25 MM_C1.114 160.66,103.19 159.38,101.92 159.38,100.65 158.43,99.69 v147.96,99.69 | JP5.P$30 111.12,159.38 109.54,157.8 97.16,157.8 95.89,156.53 v95.89,121.6 | v132.08,74.3 IC13.6
  Bottom 0.305: v95.89,121.6 v95.89,115.89 | v132.08,74.3 132.08,83.82 v147.96,99.69
P7.6  (via drill 0.5 pad 0.3)
  Top 0.305: IC13.16 111.12,73.03 109.86,74.3 v109.86,83.19 | v93.98,117.79 v118.75,117.79 162.56,117.79 163.19,117.16 MM_C1.116 | JP5.P$32 108.58,160.66 107,159.07 95.25,159.07 93.98,157.8 v93.98,121.6
  Bottom 0.305: v93.98,121.6 v93.98,117.79 | v118.75,117.79 118.75,84.14 117.79,83.19 v109.86,83.19
P7.7  (via drill 0.5 pad 0.3)
  Top 0.305: IC13.15 112.39,74.3 111.12,75.56 v111.12,81.92 | MM_C1.118 165.74,119.06 165.1,119.7 v121.28,119.7 92.71,119.7 92.08,120.33 92.08,159.07 93.34,160.34 104.78,160.34 106.05,161.61 JP5.P$34
  Bottom 0.305: v121.28,119.7 121.28,82.87 120.33,81.92 v111.12,81.92
P8.0  (via drill 0.5 pad 0.3)
  Top 0.305: MM_C1.103 149.22,102.87 149.22,106.68 148.59,107.31 v92.39,107.31 | v90.17,107.31 90.17,160.34 91.44,161.61 102.55,161.61 103.5,162.56 JP5.P$36
  Bottom 0.305: v92.39,107.31 v90.17,107.31
P8.1  (via drill 0.5 pad 0.3)
  Top 0.305: JP5.P$38 100.97,163.83 100.01,162.88 89.53,162.88 88.27,161.61 v88.27,109.22 | MM_C1.105 151.76,102.87 151.76,108.58 151.13,109.22 v92.39,109.22
  Bottom 0.305: v92.39,109.22 v88.27,109.22
P8.2  (via drill 0.5 pad 0.3)
  Top 0.305: JP5.P$40 98.42,165.42 97.16,164.15 87.63,164.15 86.36,162.88 v86.36,111.12 | MM_C1.107 154.31,102.87 154.31,110.49 153.67,111.12 v92.39,111.12
  Bottom 0.305: v92.39,111.12 v86.36,111.12
P8.3  (via drill 0.5 pad 0.3)
  Top 0.305: JP5.P$42 95.89,166.69 94.61,165.42 85.72,165.42 84.45,164.15 v84.45,113.03 | MM_C1.109 156.84,102.87 156.84,112.39 156.21,113.03 v92.39,113.03
  Bottom 0.305: v92.39,113.03 v84.45,113.03
P8.4  (via drill 0.5 pad 0.3)
  Top 0.305: JP5.P$44 93.34,167.96 92.08,166.69 83.82,166.69 82.55,165.42 v82.55,114.94 | MM_C1.111 159.38,102.87 159.38,114.3 158.75,114.94 v92.39,114.94
  Bottom 0.305: v82.55,114.94 v92.39,114.94
P8.5  (via drill 0.5 pad 0.3)
  Top 0.305: JP5.P$46 90.81,169.23 89.53,167.96 81.92,167.96 80.64,166.69 v80.64,116.84 | MM_C1.113 161.93,102.87 161.93,116.2 161.29,116.84 v92.39,116.84
  Bottom 0.305: v80.64,116.84 v92.39,116.84
P8.6  (via drill 0.5 pad 0.3)
  Top 0.305: JP5.P$48 88.27,170.5 87,169.23 80.33,169.23 79.06,167.96 79.06,147.64 78.74,147.32 v78.74,118.75 | MM_C1.115 164.47,102.87 164.47,118.11 163.83,118.75 v92.39,118.75
  Bottom 0.305: v78.74,118.75 v92.39,118.75
P8.7  (via drill 0.5 pad 0.3)
  Top 0.305: JP5.P$50 84.77,170.5 79.06,170.5 77.79,169.23 77.79,148.91 76.83,147.96 v76.83,120.65 | MM_C1.117 167,102.87 167,120.02 166.37,120.65 v93.03,120.65
  Bottom 0.305: v76.83,120.65 v93.03,120.65
RI1  (via drill 0.5 pad 0.3)
  Top 0.305: v82.23,105.41 v96.2,105.41 | L4.1 24.45,155.57 25.72,154.31 v25.72,127.64
  Bottom 0.305: MM_C1.68 101.92,104.14 100.97,103.19 100.97,96.2 100.01,95.25 97.16,95.25 96.2,96.2 v96.2,105.41 | v82.23,105.41 37.78,105.41 36.51,106.68 36.51,126.36 35.24,127.64 v25.72,127.64
RI2  (via drill 0.5 pad 0.3)
  Top 0.305: v82.23,103.5 v94.3,103.5 | 24.13,122.56 L5.1 v26.04,122.56
  Bottom 0.305: MM_C1.70 104.46,104.14 103.5,103.19 103.5,94.93 102.55,93.98 95.25,93.98 94.3,94.93 v94.3,103.5 | v82.23,103.5 35.88,103.5 34.61,104.78 34.61,121.28 33.34,122.56 v26.04,122.56
RXD
  Top 0.305: L5.2 19.64,121.92 16.51,121.92 | 16.51,121.92 C20.1 | 16.51,121.92 16.51,119.38 15.24,118.11 RS232_2.3
SCL
  Top 0.305: I2C.1 22.86,41.91 25.4,44.45 25.4,52.07 26.67,53.34 34.29,53.34 52.07,71.12 52.07,73.03 70.17,90.81 75.88,90.81 76.52,91.44 76.52,100.65 77.47,101.6 97.79,101.6 97.79,104.46 98.74,105.41 106.68,105.41 107.31,104.78 MM_C1.72
SDA
  Top 0.305: I2C.3 6.35,44.45 5.71,43.81 5.71,41.27 6.35,40.64 22.86,40.64 26.04,43.81 26.04,51.44 27.3,52.7 34.92,52.7 53.34,71.12 53.34,73.03 70.48,90.17 76.2,90.17 86.36,100.33 107,100.33 107.31,100.65 MM_C1.71
TO1  (via drill 0.5 pad 0.3)
  Top 0.305: v83.19,104.46 v95.25,104.46 | L3.1 24.13,149.22 v24.13,126.68
  Bottom 0.305: MM_C1.67 102.23,95.57 101.28,94.61 96.2,94.61 95.25,95.57 v95.25,104.46 | v83.19,104.46 36.83,104.46 35.56,105.73 35.56,125.41 34.29,126.68 v24.13,126.68
TO2  (via drill 0.5 pad 0.3)
  Top 0.305: v83.19,102.55 v93.34,102.55 | v26.04,115.57 L6.1
  Bottom 0.305: MM_C1.69 104.78,94.3 103.82,93.34 94.3,93.34 93.34,94.3 v93.34,102.55 | v83.19,102.55 34.92,102.55 33.66,103.82 33.66,114.3 32.38,115.57 v26.04,115.57
TXD
  Top 0.305: 16.51,115.57 L6.2 | 16.51,115.57 C21.1 | RS232_2.2 16.31,115.37 16.51,115.57
VAGND  (via drill 0.5 pad 0.81)
  Top 0.61: 177.16,121.92 177.16,117.47 177.8,116.84 MM_C1.133 | 177.16,121.92 MM_C1.137 | 177.16,121.92 177.16,126.36 177.8,127 MM_C1.141 | 241.3,118.11 241.34,118.15
  Top 0.813: IC4.3 C6.2 258.44,124.33 | 244.47,118.11 C2.- 241.34,118.15 | 241.3,96.52 247.01,96.52 249.56,99.06 249.56,100.33 | 225.43,93.34 225.43,71.12 252.73,71.12 254,72.39 B5.1 262.89,78.11 264.16,76.83 264.16,57.78 262.25,55.88 B7.1 | 225.43,93.34 R5.A | 210.82,177.16 130.18,177.16 128.91,175.9 JP5.P$15 | 250.19,130.18 245.32,130.18 C1.- 242.36,129.33 241.3,128.27 241.3,118.11 241.3,96.52 | 250.19,130.18 C7.2 | 250.19,130.18 IC2.GND | 258.44,124.33 258.57,124.46 | IC4.3 258.44,124.33 | 264.8,121.28 IC4.3 | 264.8,121.28 264.8,102.87 262.25,100.33 249.56,100.33 | 249.56,100.33 D8.C | 210.82,177.16 JP4.P$15 209.55,172.72 209.55,170.18 207.96,168.59 207.96,138.75 206.38,137.16 MM_C1.149 | 210.82,177.16 253.37,177.16 264.8,165.74 264.8,121.28 | 225.43,93.34 225.43,96.52 | 225.43,96.52 v225.43,97.47 | 225.43,96.52 241.3,96.52
  Top 0.864: 210.19,65.41 D4.A D3.A 211.37,69.77 212.72,71.12 R6.A 225.43,71.12
  Bottom 0.305: MM_C1.149 179.39,137.16
  Bottom 0.61: MM_C1.141 179.39,127 180.02,127.64 180.02,132.08 | 180.02,132.08 180.02,136.53 179.39,137.16 | 180.02,132.08 MM_C1.145 | MM_C1.149 MM_C1.152
VAREF  (via drill 0.5 pad 0.3)  (1 unrouted)
  Top 0.305: JP5.P$17 127,173.99 127.64,173.35 127.64,152.72 128.91,151.45 v128.91,126.36 | v184.15,154.31 184.15,174.62 184.78,175.26 207.65,175.26 208.28,174.62 JP4.P$17 | v252.09,113.03 D5.A | v212.09,175.26 v227.33,175.26
  Top 0.813: 250.19,113.03 250.19,120.02 | 250.19,120.02 IC4.2 | 250.19,123.83 R3.2 250.19,120.02
  Bottom 0.305: v128.91,126.36 147.32,126.36 153.35,132.4 164.78,132.4 170.18,127 170.18,112.71 171.13,111.76 MM_C1.130 175.9,111.44 176.85,110.49 183.2,110.49 184.15,111.44 v184.15,154.31 | v252.09,113.03 263.21,113.03 264.8,114.3 264.8,174.94 262.57,177.16 227.97,177.16 227.33,176.53 v227.33,175.26 | JP4.P$17 208.28,174.62 208.91,175.26 v212.09,175.26
VCC
  Top 0.305: R26.2 16.51,34.92 16.51,38.73 C23.1
VCC1  (via drill 0.6 pad 0.61, 0.7 pad 0.61)
  Top 0.406: v167.32,99.69 168.59,99.69 169.54,100.65 v169.54,141.92 | v167.32,84.14 v99.69,84.14 | v78.11,93.66 78.11,100.01 79.06,100.97 99.06,100.97 MM_C1.65 MM_C1.66
  Top 0.61: IC3.OUT 217.17,118.43 217.49,119.06 v217.49,135.89
  Top 0.813: IC3.OUT C12.+ | C12.+ | C12.+ C11.+ | C16.1 217.17,106.05 C11.+ | C11.+
  Bottom 0.406: MM_C1.2 178.44,146.05 177.48,145.1 172.72,145.1 v169.54,141.92 | v99.69,84.14 87.31,84.14 v78.11,93.66 | v167.32,99.69 v167.32,84.14
  Bottom 0.61: v217.49,135.89 217.49,154.62 215.58,156.53 179.39,156.53 178.44,155.57 MM_C1.1 | MM_C1.1 178.44,149.54 | MM_C1.2 MM_C1.1
VCC2  (via drill 0.5, 0.5 pad 0.81, 0.9)  (7 unrouted)
  Top 0.305: D14.C 224.79,55.97 | 224.79,55.97 225.97,55.97 226.06,55.88 | 224.79,55.97 224.79,55.88 224.88,55.97 D16.C | R39.1 228.81,45.3 228.6,45.09 R41.1 225,45.3 224.79,45.09 R40.2 221.19,45.3 220.98,45.09 R38.2 217.38,45.3 217.17,45.09 R37.2 213.57,45.3 213.36,45.09 R36.2 R47.2 209.13,45.3 | R46.2 201.93,46.35 203.2,47.62 209.55,47.62 | IC15.4 193.04,64.77 194.94,62.87 196.22,62.87 196.85,62.23 IC15.8 196.85,56.83 | 196.85,56.83 209.55,56.83 | R53.2 142.88,31.33 142.88,34.92 R54.2 142.88,35.14 142.88,38.73 R55.2 142.88,38.95 v142.88,40.64 | 156.21,38.73 v156.21,40.64 | v156.21,40.64 156.21,42.33 R57.2 156.21,42.55 v156.21,40.64 | 156.21,38.73 R58.2 | 156.21,38.73 156.21,34.92 R60.2 156.21,34.71 156.21,31.11 | v142.88,40.64 142.88,42.33 R56.2 142.88,42.55 v142.88,40.64 | OK1.2 26.67,95.89 25.4,94.61 25.4,88.27 26.67,87 OK2.8 OK2.7 | JP9.3 5.71,62.23 6.99,60.96 12.06,60.96 12.7,61.59 12.7,64.77 14.61,66.67 21.59,66.67 23.5,68.58 v24.77,68.58 | 31.75,68.58 v29.84,68.58 | 31.75,66.67 C36.2 | 31.75,66.67 31.75,68.58 | 31.75,70.48 C28.1 | 31.75,68.58 31.75,70.48 | 31.75,70.48 30.48,71.75 30.48,74.3 26.04,78.74 26.04,83.19 27.3,84.45 OK2.7 | v29.84,66.67 31.75,66.67 | v77.79,35.88 74.3,35.88 | 74.3,35.88 v72.39,35.88 | 83.5,35.88 v81.92,35.88 | v87,35.88 83.5,35.88 | 93.03,35.88 v91.44,35.88 | v96.84,35.88 93.03,35.88 | v100.97,35.88 102.87,35.88 v106.05,35.88 | v115.57,35.88 112.08,35.88 | 112.08,35.88 v110.49,35.88 | 121.6,35.88 v120.02,35.88 | v40.01,39.37 40.01,43.18 39.37,43.81 36.83,43.81 | 36.83,43.81 v29.84,43.81 | R8.2 36.83,40.64 36.83,43.81 | IC12.9 81.92,68.58 v84.45,71.12 | IC10.20 v97.79,71.12 102.23,71.12 103.5,69.85 R27.2 105.19,69.43 106.68,67.94 118.75,67.94
  Top 0.305: 118.75,67.94 IC13.20 | 196.85,56.83 196.85,55.88 195.58,54.61 182.88,54.61 v182.25,53.98 IC14.14 | 156.21,31.11 R61.2 | 156.21,31.11 156.21,29.84 v156.84,29.21 | v160.02,29.21 160.66,29.84 160.66,31.11 | v173.99,53.98 170.81,53.98 R59.1 168.69,53.76 167.64,52.7 v167.64,33.66 | 160.66,31.11 R62.2 | v160.66,33.66 160.66,31.11 | IC18.20 139.65,55.83 139.7,55.88 134.62,55.88 | 134.62,55.88 v134.62,40.64 v134.62,35.88 | 134.62,55.88 126.68,55.88 118.75,63.82 118.75,67.94 | IC9.20 70.53,82.51 71.12,81.92 83.82,81.92 v84.45,82.55 | v30.48,109.22 49.53,109.22 50.48,110.17 SPEAKER.+ | R52.2 32.7,84.14 32.38,84.45 OK2.7 | 55.24,34.29 55.03,34.19 55.03,31.33 | 64.77,34.29 64.56,34.19 64.56,31.22 64.77,31.11 R11.2 | R34.2 64.77,37.47 64.56,37.36 64.56,35.88 | IC5.14 64.77,44.13 62.87,42.23 v62.87,35.88 64.56,35.88 | 55.24,34.29 R10.2 | 55.03,35.88 55.03,34.39 55.24,34.29 | 55.03,35.88 R35.2 | 64.77,34.29 R12.2 | 64.56,35.88 64.56,34.39 64.77,34.29 | 55.03,35.88 v53.02,35.88 | v57.15,35.88 55.03,35.88 | v68.26,35.88 64.56,35.88 | 74.3,35.88 74.3,34.29 | R13.2 74.3,31.11 74.3,34.29 | 74.3,34.29 R14.2 | R33.2 74.3,37.47 74.3,35.88 | IC6.14 83.82,46.99 81.6,44.45 81.6,38.1 82.23,37.47 R32.2 83.61,35.98 83.5,35.88 | 83.61,37.25 R16.2 R15.2 83.61,31.01 | 93.03,34.29 R18.2 | 93.03,35.88 93.03,34.29 | 93.45,31.01 93.66,30.8 | 93.45,31.01 R17.2 | 93.03,34.29 93.03,31.11 93.45,31.01 | 93.03,35.88 93.03,37.47 | R19.2 102.55,31.11 102.66,31.22 R20.2 R30.2 | R30.2 102.66,37.57 102.87,37.78 | IC7.14 102.87,46.99 100.65,44.77 100.65,38.1 101.28,37.47 R30.2 | R21.2 R22.2 112.18,34.51 112.08,34.61 112.08,35.88 | R29.2 112.08,37.47 112.08,35.88
  Top 0.305: R23.2 121.7,34.08 121.92,34.29 R24.2 121.7,37.25 | 121.7,37.25 121.92,37.47 R28.2 120.33,37.47 119.7,38.1 119.7,44.77 121.92,46.99 IC8.14 | 121.7,37.25 121.7,35.98 121.6,35.88 | v126.68,35.88 121.6,35.88 | C8.+ 245.07,143.79 245.11,143.83 245.11,143.19
  Top 0.813: 240.03,159.38 240.03,165.74 239.29,166.47 R7.2 230.09,166.47 228.6,167.96 JP4.P$2 | IC1.OUT 233.04,158.75 231.56,157.26 C5.1 217.17,149.86 215.9,148.59 215.9,137.79 | C8.+ v251.46,143.51 | 214,85.09 210.19,85.09 D1.C 210.19,84.45 | 214,85.09 219.07,85.09 R5.E 223.52,80.64 v223.52,74.93 | 214,85.09 214,92.71 212.64,94.06 D2.C v210.19,97.79 | v223.52,63.5 223.52,62.23 222.25,60.96 R6.E 220.98,58.1 | 215.9,137.79 215.9,121.28 210.19,115.57 v210.19,107.31 | 215.9,137.79 243.21,137.79 245.11,139.7 245.11,143.19 | 220.98,58.1 220.98,55.88 | R47.2 209.55,47.62 209.55,56.83 210.82,58.1 220.98,58.1 | JP4.P$4 JP4.P$2 | JP4.P$2 228.6,171.13
  Top 0.914: D2.C 210.19,93.98
  Bottom 0.305: v156.21,40.64 v142.88,40.64 v134.62,40.64 | v29.84,68.58 v24.77,68.58 | v29.84,43.81 v29.84,66.67 | v72.39,35.88 v68.26,35.88 | v81.92,35.88 v77.79,35.88 | v91.44,35.88 v87,35.88 | v100.97,35.88 v96.84,35.88 | v110.49,35.88 v106.05,35.88 | v120.02,35.88 v115.57,35.88 | v53.02,35.88 40.96,35.88 40.01,36.83 v40.01,39.37 | v62.87,35.88 v57.15,35.88 | v97.79,71.12 v84.45,71.12 v84.45,82.55 | v160.02,29.21 v156.84,29.21 | v182.25,53.98 v173.99,53.98 | v167.64,33.66 v160.66,33.66 | v134.62,35.88 v126.68,35.88 | JP5.P$4 JP5.P$2 | JP3.P$2 JP3.P$4 | OK1.2 29.84,95.89 30.48,96.52 v30.48,109.22
  Bottom 0.61: JP4.P$4 224.79,172.72 148.27,172.72 147,171.45 JP5.P$4 142.88,172.72 78.74,172.72 JP3.P$2 JP3.P$4
  Bottom 0.813: v251.46,143.51 252.09,143.51 254,145.41 B2.1 | v223.52,63.5 v223.52,74.93 | v210.19,97.79 v210.19,107.31
VCC3
  Top 0.305: JP11.2 JP13.2

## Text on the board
Top: Projektarbeit SS07 | Laborplatine C167 | Betreuer: Prof. Beetz | (c) Leidner, Oraschewski, Widmann, Herbster, Seybold, Stone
